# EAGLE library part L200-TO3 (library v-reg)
VOLTAGE REGULATOR
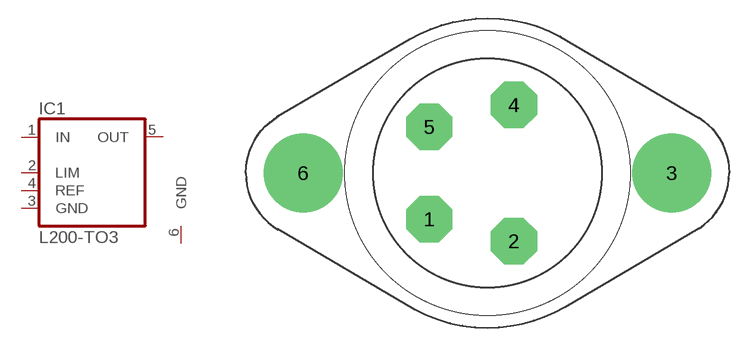
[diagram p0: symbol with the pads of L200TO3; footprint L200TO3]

Designator prefix IC; gates 1=L200 G$1=GND

## L200-TO3  [L200TO3]
1  1:IN  in
2  1:LIM  in
3  1:GND  pas
4  1:REF  in
5  1:OUT  pas
6  G$1:GND  pwr

## Footprint L200TO3 (pad centres in mm)
VOLTAGE REGULATOR
drill 1.194 pad 3.81 octagon: 1 -4.775,-3.785; 2 2.159,-5.588; 4 2.159,5.588; 5 -4.775,3.785
drill 4.115 pad 6.477 round: 3 15.113,0; 6 -15.113,0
